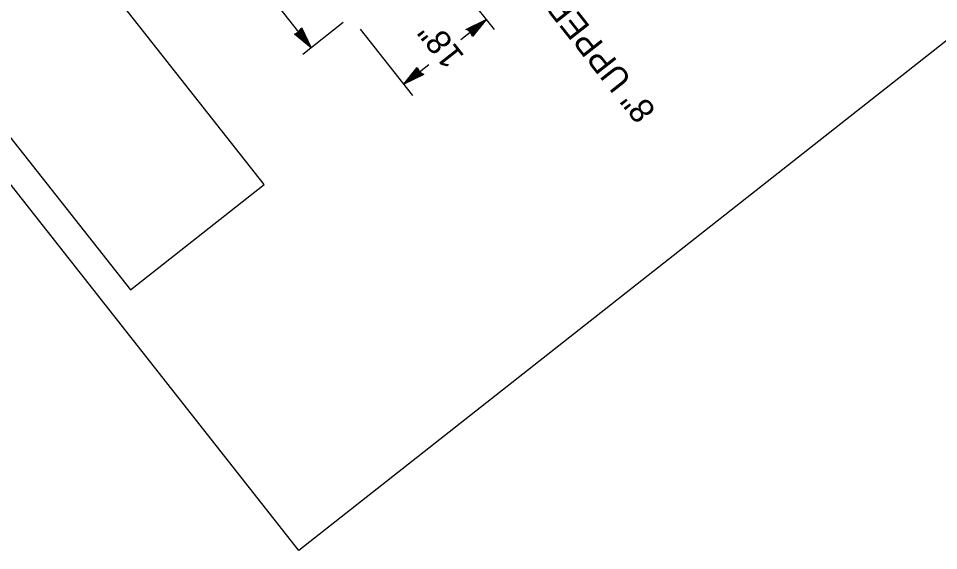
# Model space of a CAD drawing. Extents: x 672438 to 673763, y 1673171 to 1675010.
# Drawn here: x 673288.4 to 673446.4, y 1674628.2 to 1674719.6 of the extents above; entities that cross this region are included whole.
import ezdxf

# ---------------------------------------------------------------- set-up
doc = ezdxf.new("R2010")
doc.units = 0
doc.layers.add('61', color=7, linetype='Continuous')
doc.layers.add('Level 1', color=7, linetype='Continuous')

msp = doc.modelspace()

# ---------------------------------------------------------------- linework, layer by layer
at = {"layer": '61'}
msp.add_lwpolyline([(673330.59, 1674691.06), (673257.06, 1674784.33), (673234.11, 1674766.24), (673307.64, 1674672.97)], close=True, dxfattribs=at)
at = {"layer": 'Level 1'}
for p, q in [((673596.12, 1674832.77), (673336.59, 1674628.17)), ((673336.59, 1674628.17), (673196.8, 1674805.49)), ((673338.71, 1674714.55), (673324.1, 1674733.09)), ((673361.25, 1674728.87), (673370.08, 1674717.67)), ((673364.37, 1674715.99), (673368.71, 1674719.41)), ((673365.25, 1674717.71), (673368.71, 1674719.41)), ((673365.44, 1674717.76), (673368.29, 1674719.05)), ((673365.61, 1674717.72), (673368.45, 1674719.14)), ((673368.71, 1674719.41), (673366.39, 1674716.5)), ((673368.49, 1674719.17), (673366.41, 1674716.65)), ((673368.24, 1674719.11), (673367.44, 1674718.69)), ((673368.45, 1674719.14), (673368.24, 1674719.11)), ((673368.29, 1674719.05), (673368.49, 1674719.17)), ((673336.25, 1674716.85), (673336.95, 1674717.53)), ((673336.38, 1674716.99), (673336.95, 1674717.53)), ((673336.52, 1674717.2), (673336.99, 1674717.87)), ((673336.56, 1674717.27), (673336.87, 1674717.51)), ((673336.87, 1674717.51), (673337.06, 1674717.82)), ((673336.99, 1674717.87), (673336.93, 1674717.65)), ((673336.93, 1674717.65), (673337.02, 1674717.66)), ((673336.95, 1674717.53), (673337.98, 1674715.41)), ((673336.95, 1674717.53), (673338.1, 1674715.34)), ((673337.01, 1674718.01), (673338.71, 1674714.55)), ((673337.02, 1674717.66), (673338.44, 1674714.81)), ((673337.06, 1674717.82), (673338.35, 1674714.97)), ((673344.17, 1674718.86), (673337.27, 1674713.41)), ((673347.11, 1674717.73), (673356.07, 1674706.37)), ((673366.07, 1674717.21), (673365.4, 1674717.69)), ((673365.4, 1674717.69), (673365.62, 1674717.62)), ((673365.76, 1674717.57), (673365.44, 1674717.76)), ((673365.62, 1674717.62), (673365.61, 1674717.72)), ((673365.73, 1674717.65), (673367.92, 1674718.8)), ((673365.73, 1674717.65), (673367.85, 1674718.67)), ((673366.27, 1674717.08), (673365.73, 1674717.65)), ((673366.41, 1674716.95), (673365.73, 1674717.65)), ((673366, 1674717.26), (673365.76, 1674717.57)), ((673365.91, 1674717.59), (673367.42, 1674718.34)), ((673366.37, 1674717.08), (673365.91, 1674717.59)), ((673366.35, 1674717.5), (673365.99, 1674717.49)), ((673365.99, 1674717.49), (673366.36, 1674717.21)), ((673366.07, 1674717.55), (673367.03, 1674718.07)), ((673366.42, 1674717.23), (673366.07, 1674717.55)), ((673366.18, 1674717.5), (673366.69, 1674717.77)), ((673366.46, 1674717.35), (673366.18, 1674717.5)), ((673366.43, 1674717.43), (673366.35, 1674717.5)), ((673366.36, 1674717.21), (673366.87, 1674717.97)), ((673367.92, 1674718.8), (673366.37, 1674717.08)), ((673368.14, 1674718.9), (673366.41, 1674716.82)), ((673367.85, 1674718.67), (673366.41, 1674716.95)), ((673367.42, 1674718.34), (673366.42, 1674717.23)), ((673366.69, 1674717.77), (673366.43, 1674717.43)), ((673367.03, 1674718.07), (673366.46, 1674717.35)), ((673366.87, 1674717.97), (673367.12, 1674718.07)), ((673367.49, 1674718.42), (673367.05, 1674718.21)), ((673367.12, 1674718.07), (673367.49, 1674718.42)), ((673367.44, 1674718.69), (673368.14, 1674718.9)), ((673335.8, 1674716.87), (673336.56, 1674717.27)), ((673338.71, 1674714.55), (673335.8, 1674716.87)), ((673335.95, 1674716.85), (673336.52, 1674717.2)), ((673338.48, 1674714.77), (673335.95, 1674716.85)), ((673336.12, 1674716.85), (673336.38, 1674716.99)), ((673338.2, 1674715.12), (673336.12, 1674716.85)), ((673337.98, 1674715.41), (673336.25, 1674716.85)), ((673336.38, 1674716.89), (673336.89, 1674717.36)), ((673338.1, 1674715.34), (673336.38, 1674716.89)), ((673336.79, 1674717.27), (673336.52, 1674716.9)), ((673336.52, 1674716.9), (673337.27, 1674716.39)), ((673336.53, 1674716.84), (673336.85, 1674717.19)), ((673337.64, 1674715.85), (673336.53, 1674716.84)), ((673336.66, 1674716.8), (673336.8, 1674717.09)), ((673337.37, 1674716.23), (673336.66, 1674716.8)), ((673336.73, 1674716.83), (673336.8, 1674716.92)), ((673337.07, 1674716.57), (673336.73, 1674716.83)), ((673336.8, 1674716.92), (673336.79, 1674717.27)), ((673336.8, 1674717.09), (673337.07, 1674716.57)), ((673336.85, 1674717.19), (673337.37, 1674716.23)), ((673336.89, 1674717.36), (673337.64, 1674715.85)), ((673337.27, 1674716.39), (673337.37, 1674716.14)), ((673337.37, 1674716.14), (673337.72, 1674715.78)), ((673337.72, 1674715.78), (673337.51, 1674716.21)), ((673366.39, 1674716.5), (673366, 1674717.26)), ((673366.41, 1674716.65), (673366.07, 1674717.21)), ((673366.41, 1674716.82), (673366.27, 1674717.08)), ((673338.41, 1674715.02), (673337.99, 1674715.82)), ((673337.99, 1674715.82), (673338.2, 1674715.12)), ((673338.35, 1674714.97), (673338.48, 1674714.77)), ((673338.44, 1674714.81), (673338.41, 1674715.02)), ((673354.58, 1674708.27), (673358.9, 1674711.68)), ((673354.58, 1674708.27), (673356.9, 1674711.17)), ((673356.9, 1674711.17), (673357.29, 1674710.41)), ((673358.04, 1674709.97), (673354.58, 1674708.27)), ((673354.79, 1674708.5), (673356.88, 1674711.03)), ((673357.68, 1674709.96), (673354.84, 1674708.53)), ((673357.85, 1674709.92), (673355, 1674708.63)), ((673355.14, 1674708.78), (673356.88, 1674710.86)), ((673355.36, 1674708.88), (673356.92, 1674710.59)), ((673357.56, 1674710.03), (673355.36, 1674708.88)), ((673355.44, 1674709), (673356.88, 1674710.73)), ((673357.56, 1674710.03), (673355.44, 1674709)), ((673356.16, 1674709.6), (673355.8, 1674709.25)), ((673355.87, 1674709.34), (673356.86, 1674710.45)), ((673357.38, 1674710.09), (673355.87, 1674709.34)), ((673356.42, 1674709.7), (673356.16, 1674709.6)), ((673356.26, 1674709.61), (673356.83, 1674710.32)), ((673357.22, 1674710.13), (673356.26, 1674709.61)), ((673356.92, 1674710.46), (673356.42, 1674709.7)), ((673356.59, 1674709.9), (673356.86, 1674710.24)), ((673357.11, 1674710.18), (673356.59, 1674709.9)), ((673356.83, 1674710.32), (673357.11, 1674710.18)), ((673356.86, 1674710.45), (673357.22, 1674710.13)), ((673356.86, 1674710.24), (673356.94, 1674710.18)), ((673356.88, 1674711.03), (673357.22, 1674710.46)), ((673356.88, 1674710.86), (673357.01, 1674710.6)), ((673356.88, 1674710.73), (673357.56, 1674710.03)), ((673356.92, 1674710.59), (673357.38, 1674710.09)), ((673357.3, 1674710.19), (673356.92, 1674710.46)), ((673356.94, 1674710.18), (673357.3, 1674710.19)), ((673357.01, 1674710.6), (673357.56, 1674710.03)), ((673357.22, 1674710.46), (673357.89, 1674709.99)), ((673357.29, 1674710.41), (673357.53, 1674710.11)), ((673357.53, 1674710.11), (673357.85, 1674709.92)), ((673357.89, 1674709.99), (673357.67, 1674710.05)), ((673357.67, 1674710.05), (673357.68, 1674709.96)), ((673355, 1674708.63), (673354.79, 1674708.5)), ((673354.84, 1674708.53), (673355.04, 1674708.56)), ((673355.04, 1674708.56), (673355.84, 1674708.99)), ((673355.84, 1674708.99), (673355.14, 1674708.78)), ((673355.8, 1674709.25), (673356.24, 1674709.46))]:
    msp.add_line(p, q, dxfattribs=at)

# ---------------------------------------------------------------- texts
for s, p in [('8" UPPERCASE', (673398.01, 1674703.79)), ('18"', (673365.12, 1674713.1))]:
    msp.add_text(s, height=4.2, rotation=128.2505, dxfattribs=at).set_placement(p)

doc.saveas('drawing.dxf')
